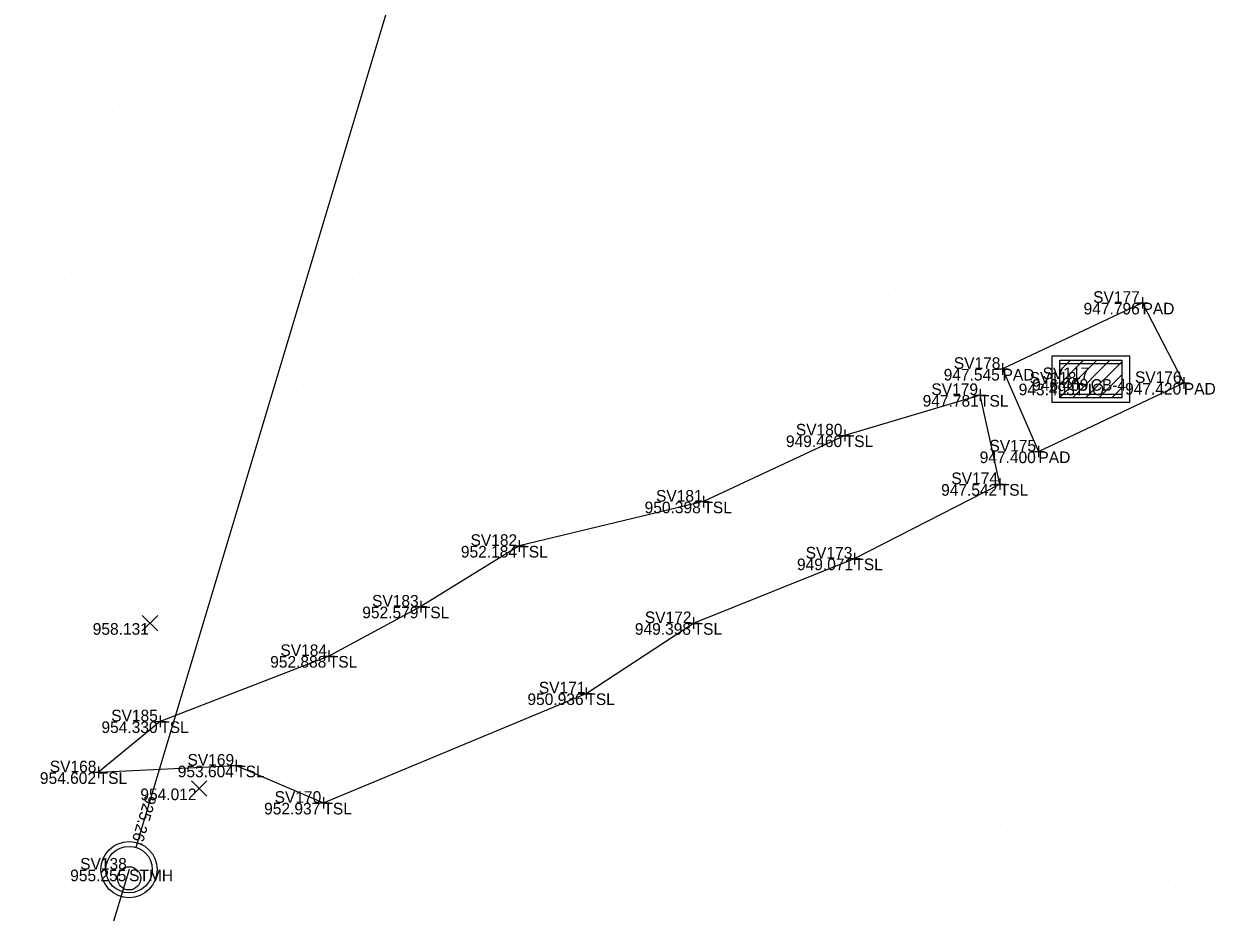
# Model space of a CAD drawing. Extents: x 2262025 to 2264532, y 740981 to 742724.
# Drawn here: x 2262974.6 to 2263077.7, y 741889.5 to 741965.9 of the extents above; entities that cross this region are included whole.
import ezdxf

# ---------------------------------------------------------------- set-up
doc = ezdxf.new("R2010")
doc.units = 0
for name, color, linetype in [('DR_X_Storm_Sewer', 7, 'Continuous'), ('GE_X_Alignment_1000_Bearings', 7, 'Continuous'), ('GE_X_Alignment_500_Cardinal_Points', 7, 'Continuous'), ('Ground Shots', 7, 'Continuous'), ('HY_X_Spring_Cells', 7, 'Continuous'), ('RS_Raster1', 7, 'Continuous'), ('RW_X_CL', 7, 'Continuous'), ('RW_X_CL_100_Cardinal_Points', 7, 'Continuous'), ('RW_X_CL_100_Curve_Data', 7, 'Continuous'), ('RW_X_CL_100_Stations', 7, 'Continuous'), ('RW_X_CL_500_Bearings', 7, 'Continuous'), ('RW_X_CL_500_Curve_Data', 7, 'Continuous'), ('RW_X_CL_500_Stations', 7, 'Continuous'), ('SV_X_Text_Comment', 7, 'Continuous')]:
    doc.layers.add(name, color=color, linetype=linetype)

msp = doc.modelspace()

# ---------------------------------------------------------------- linework, layer by layer
at = {"layer": 'DR_X_Storm_Sewer'}
msp.add_line((2263148.87, 742443.51), (2262984.25, 741895.04), dxfattribs=at)
msp.add_line((2263148.87, 742443.51), (2262984.25, 741895.04), dxfattribs=at)
at = {"layer": 'GE_X_Alignment_1000_Bearings'}
msp.add_line((2262986.36, 741905.89), (2262981.06, 741901.51), dxfattribs=at)
msp.add_lwpolyline([(2262981.06, 741901.51), (2262992.9, 741902.08), (2263000.41, 741898.88), (2263023.05, 741908.3), (2263032.29, 741914.35), (2263046.13, 741919.91), (2263058.65, 741926.32), (2263056.95, 741933.99), (2263045.3, 741930.51), (2263033.13, 741924.81), (2263017.28, 741921), (2263008.8, 741915.77), (2263000.88, 741911.52), (2262986.36, 741905.89)], dxfattribs=at)
at = {"layer": 'GE_X_Alignment_500_Cardinal_Points'}
for p, q in [((2262984.82, 741913.68), (2262986.16, 741915.02)), ((2262984.82, 741915.02), (2262986.16, 741913.68)), ((2262989.04, 741899.44), (2262990.37, 741900.77)), ((2262989.04, 741900.77), (2262990.37, 741899.44))]:
    msp.add_line(p, q, dxfattribs=at)
at = {"layer": 'Ground Shots'}
for p, q in [((2262977.78, 741964.05), (2262977.78, 741964.05)), ((2262987.89, 741964.11), (2262987.89, 741964.11)), ((2262997.78, 741964.05), (2262997.78, 741964.05)), ((2263002.86, 741964.01), (2263002.86, 741964.01)), ((2263007.85, 741964.01), (2263007.85, 741964.01)), ((2263013.06, 741964), (2263013.06, 741964)), ((2263017.95, 741964.01), (2263017.95, 741964.01)), ((2262992.72, 741963.93), (2262992.72, 741963.93)), ((2263023.1, 741963.95), (2263023.1, 741963.95)), ((2263027.97, 741963.9), (2263027.97, 741963.9)), ((2263039.17, 741962.7), (2263039.17, 741962.7)), ((2263044.03, 741962.73), (2263044.03, 741962.73)), ((2263049.08, 741962.59), (2263049.08, 741962.59)), ((2263054.04, 741962.61), (2263054.04, 741962.61)), ((2263074.22, 741962.68), (2263074.22, 741962.68)), ((2262977.87, 741959), (2262977.87, 741959)), ((2262982.88, 741959), (2262982.88, 741959)), ((2262987.81, 741959.1), (2262987.81, 741959.1)), ((2262993.22, 741958.93), (2262993.22, 741958.93)), ((2262997.81, 741959), (2262997.81, 741959)), ((2263002.53, 741958.99), (2263002.53, 741958.99)), ((2263012.72, 741959.33), (2263012.72, 741959.33)), ((2263027.82, 741958.8), (2263027.82, 741958.8)), ((2263063.8, 741958.18), (2263063.8, 741958.18)), ((2263073.89, 741957.83), (2263073.89, 741957.83)), ((2263034.06, 741957.47), (2263034.06, 741957.47)), ((2263039.02, 741957.76), (2263039.02, 741957.76)), ((2263044.2, 741957.53), (2263044.2, 741957.53)), ((2263048.71, 741957.73), (2263048.71, 741957.73)), ((2262977.9, 741954.03), (2262977.9, 741954.03)), ((2262982.64, 741953.86), (2262982.64, 741953.86)), ((2262987.68, 741953.97), (2262987.68, 741953.97)), ((2262992.99, 741953.89), (2262992.99, 741953.89)), ((2262997.81, 741954.05), (2262997.81, 741954.05)), ((2263003.2, 741953.68), (2263003.2, 741953.68)), ((2263007.91, 741953.88), (2263007.91, 741953.88)), ((2263012.97, 741953.9), (2263012.97, 741953.9)), ((2263022.62, 741953.86), (2263022.62, 741953.86)), ((2263027.93, 741954.09), (2263027.93, 741954.09)), ((2263074.31, 741953.11), (2263074.31, 741953.11)), ((2263044.21, 741952.42), (2263044.21, 741952.42)), ((2262977.96, 741948.8), (2262977.96, 741948.8)), ((2262982.92, 741948.92), (2262982.92, 741948.92)), ((2262987.8, 741949.09), (2262987.8, 741949.09)), ((2262992.95, 741948.94), (2262992.95, 741948.94)), ((2262997.96, 741948.85), (2262997.96, 741948.85)), ((2263002.58, 741948.79), (2263002.58, 741948.79)), ((2263007.83, 741948.92), (2263007.83, 741948.92)), ((2263017.86, 741948.95), (2263017.86, 741948.95)), ((2263027.83, 741948.74), (2263027.83, 741948.74)), ((2263039.03, 741947.72), (2263039.03, 741947.72)), ((2263044.31, 741947.68), (2263044.31, 741947.68)), ((2263049, 741947.6), (2263049, 741947.6)), ((2262978.08, 741943.92), (2262978.08, 741943.92)), ((2262982.84, 741944.05), (2262982.84, 741944.05)), ((2262987.8, 741944.07), (2262987.8, 741944.07)), ((2262992.77, 741944.11), (2262992.77, 741944.11)), ((2262997.83, 741943.88), (2262997.83, 741943.88)), ((2263002.9, 741943.97), (2263002.9, 741943.97)), ((2263008.06, 741943.97), (2263008.06, 741943.97)), ((2263012.8, 741944.32), (2263012.8, 741944.32)), ((2263018.17, 741944.32), (2263018.17, 741944.32)), ((2263022.52, 741944.1), (2263022.52, 741944.1)), ((2263028.09, 741943.85), (2263028.09, 741943.85)), ((2263049.04, 741942.58), (2263049.04, 741942.58)), ((2263054.22, 741943), (2263054.22, 741943)), ((2262977.59, 741939.17), (2262977.59, 741939.17)), ((2262982.88, 741938.94), (2262982.88, 741938.94)), ((2262992.98, 741938.86), (2262992.98, 741938.86)), ((2263003.1, 741938.87), (2263003.1, 741938.87)), ((2263039.17, 741937.71), (2263039.17, 741937.71)), ((2263043.96, 741937.7), (2263043.96, 741937.7)), ((2262998.13, 741934.31), (2262998.13, 741934.31)), ((2262978.02, 741933.85), (2262978.02, 741933.85)), ((2262982.77, 741933.92), (2262982.77, 741933.92)), ((2262987.92, 741934.02), (2262987.92, 741934.02)), ((2262992.93, 741933.85), (2262992.93, 741933.85)), ((2263002.69, 741934.03), (2263002.69, 741934.03)), ((2263038.95, 741933.19), (2263038.95, 741933.19)), ((2262977.8, 741929.1), (2262977.8, 741929.1)), ((2262982.98, 741929.1), (2262982.98, 741929.1)), ((2262987.91, 741929.08), (2262987.91, 741929.08)), ((2262977.78, 741924.52), (2262977.78, 741924.52)), ((2263073.57, 741906.83), (2263073.57, 741906.83)), ((2263058.66, 741901.69), (2263058.66, 741901.69)), ((2263063.77, 741901.96), (2263063.77, 741901.96)), ((2263068.59, 741901.85), (2263068.59, 741901.85)), ((2263073.62, 741901.52), (2263073.62, 741901.52)), ((2263058.68, 741897.03), (2263058.68, 741897.03)), ((2263063.6, 741897.11), (2263063.6, 741897.11)), ((2263068.56, 741897.06), (2263068.56, 741897.06)), ((2263043.46, 741896.56), (2263043.46, 741896.56)), ((2263048.46, 741896.88), (2263048.46, 741896.88)), ((2263053.56, 741896.87), (2263053.56, 741896.87)), ((2263073.57, 741896.78), (2263073.57, 741896.78)), ((2263033.48, 741892.09), (2263033.48, 741892.09)), ((2263038.64, 741891.93), (2263038.64, 741891.93)), ((2263043.54, 741891.89), (2263043.54, 741891.89)), ((2263048.75, 741891.89), (2263048.75, 741891.89)), ((2263058.49, 741891.93), (2263058.49, 741891.93)), ((2263063.73, 741892.08), (2263063.73, 741892.08)), ((2263068.55, 741891.88), (2263068.55, 741891.88)), ((2263073.15, 741892.2), (2263073.15, 741892.2)), ((2263028.77, 741891.51), (2263028.77, 741891.51)), ((2263053.54, 741891.7), (2263053.54, 741891.7))]:
    msp.add_line(p, q, dxfattribs=at)
at = {"layer": 'RW_X_CL_100_Cardinal_Points'}
for p, q in [((2263070.94, 741942.43), (2263070.94, 741941.43)), ((2263070.44, 741941.93), (2263071.44, 741941.93)), ((2263070.94, 741941.93), (2263070.94, 741941.93)), ((2263058.39, 741936.24), (2263059.39, 741936.24)), ((2263058.89, 741936.74), (2263058.89, 741935.74)), ((2263058.89, 741936.24), (2263058.89, 741936.24)), ((2263074.5, 741935.53), (2263074.5, 741934.53)), ((2263056.95, 741934.49), (2263056.95, 741933.49)), ((2263074, 741935.03), (2263075, 741935.03)), ((2263074.5, 741935.03), (2263074.5, 741935.03)), ((2263056.45, 741933.99), (2263057.45, 741933.99)), ((2263056.95, 741933.99), (2263056.95, 741933.99)), ((2263045.3, 741931.01), (2263045.3, 741930.01)), ((2263044.8, 741930.51), (2263045.8, 741930.51)), ((2263045.3, 741930.51), (2263045.3, 741930.51)), ((2263061.48, 741929.13), (2263062.48, 741929.13)), ((2263061.98, 741929.63), (2263061.98, 741928.63)), ((2263061.98, 741929.13), (2263061.98, 741929.13)), ((2263058.15, 741926.32), (2263059.15, 741926.32)), ((2263058.65, 741926.82), (2263058.65, 741925.82)), ((2263058.65, 741926.32), (2263058.65, 741926.32)), ((2263032.63, 741924.81), (2263033.63, 741924.81)), ((2263033.13, 741925.31), (2263033.13, 741924.31)), ((2263033.13, 741924.81), (2263033.13, 741924.81)), ((2263016.78, 741921), (2263017.78, 741921)), ((2263017.28, 741921.5), (2263017.28, 741920.5)), ((2263017.28, 741921), (2263017.28, 741921)), ((2263045.63, 741919.91), (2263046.63, 741919.91)), ((2263046.13, 741920.41), (2263046.13, 741919.41)), ((2263046.13, 741919.91), (2263046.13, 741919.91)), ((2263008.3, 741915.77), (2263009.3, 741915.77)), ((2263008.8, 741916.27), (2263008.8, 741915.27)), ((2263008.8, 741915.77), (2263008.8, 741915.77)), ((2263032.29, 741914.85), (2263032.29, 741913.85)), ((2263031.79, 741914.35), (2263032.79, 741914.35)), ((2263032.29, 741914.35), (2263032.29, 741914.35)), ((2263000.38, 741911.52), (2263001.38, 741911.52)), ((2263000.88, 741912.02), (2263000.88, 741911.02)), ((2263000.88, 741911.52), (2263000.88, 741911.52)), ((2263023.05, 741908.8), (2263023.05, 741907.8)), ((2263022.55, 741908.3), (2263023.55, 741908.3)), ((2263023.05, 741908.3), (2263023.05, 741908.3)), ((2262986.36, 741906.39), (2262986.36, 741905.39)), ((2262985.86, 741905.89), (2262986.86, 741905.89)), ((2262986.36, 741905.89), (2262986.36, 741905.89)), ((2262992.9, 741902.58), (2262992.9, 741901.58)), ((2262980.56, 741901.51), (2262981.56, 741901.51)), ((2262981.06, 741902.01), (2262981.06, 741901.01)), ((2262981.06, 741901.51), (2262981.06, 741901.51)), ((2262992.4, 741902.08), (2262993.4, 741902.08)), ((2262992.9, 741902.08), (2262992.9, 741902.08)), ((2263000.41, 741899.38), (2263000.41, 741898.38)), ((2262999.91, 741898.88), (2263000.91, 741898.88)), ((2263000.41, 741898.88), (2263000.41, 741898.88))]:
    msp.add_line(p, q, dxfattribs=at)
at = {"layer": 'RW_X_CL_100_Curve_Data'}
for p, q in [((2263063.82, 741933.79), (2263067, 741936.98)), ((2263063.82, 741934.93), (2263065.87, 741936.98)), ((2263063.82, 741936.06), (2263064.74, 741936.98)), ((2263063.82, 741933.79), (2263067, 741936.98)), ((2263063.82, 741934.93), (2263065.87, 741936.98)), ((2263063.82, 741936.06), (2263064.74, 741936.98)), ((2263064.9, 741933.75), (2263068.13, 741936.98)), ((2263064.9, 741933.75), (2263068.13, 741936.98)), ((2263066.03, 741933.75), (2263069.15, 741936.86)), ((2263066.03, 741933.75), (2263069.15, 741936.86)), ((2263067.17, 741933.75), (2263069.15, 741935.73)), ((2263067.17, 741933.75), (2263069.15, 741935.73)), ((2263068.3, 741933.75), (2263069.15, 741934.6)), ((2263068.3, 741933.75), (2263069.15, 741934.6))]:
    msp.add_line(p, q, dxfattribs=at)
for points in [[(2263063.15, 741937.36), (2263069.82, 741937.36), (2263069.82, 741933.36), (2263063.15, 741933.36)], [(2263063.15, 741937.36), (2263069.82, 741937.36), (2263069.82, 741933.36), (2263063.15, 741933.36)], [(2263063.82, 741936.98), (2263069.15, 741936.98), (2263069.15, 741933.75), (2263063.82, 741933.75)], [(2263063.82, 741936.98), (2263069.15, 741936.98), (2263069.15, 741933.75), (2263063.82, 741933.75)], [(2263063.82, 741936.7), (2263069.15, 741936.7), (2263069.15, 741934.03), (2263063.82, 741934.03)], [(2263063.82, 741936.7), (2263069.15, 741936.7), (2263069.15, 741934.03), (2263063.82, 741934.03)]]:
    msp.add_lwpolyline(points, close=True, dxfattribs=at)
for centre, radius in [((2262983.68, 741893.13), 2.42), ((2262983.68, 741893.13), 2.42), ((2262983.68, 741893.13), 2), ((2262983.68, 741893.13), 2), ((2262983.68, 741892.38), 1), ((2262983.68, 741892.38), 1)]:
    msp.add_circle(centre, radius, dxfattribs=at)
at = {"layer": 'RW_X_CL_100_Stations'}
for p, q in [((2263066.48, 741937.36), (2263066.48, 741937.36)), ((2263066.48, 741937.36), (2263066.48, 741937.36)), ((2263066.48, 741936.7), (2263066.48, 741936.7)), ((2263066.48, 741936.7), (2263066.48, 741936.7)), ((2263063.82, 741935.36), (2263063.82, 741935.36)), ((2263063.82, 741935.36), (2263063.82, 741935.36)), ((2263066.48, 741935.36), (2263066.48, 741935.36)), ((2263066.48, 741935.36), (2263066.48, 741935.36)), ((2263066.48, 741935.36), (2263066.48, 741935.36)), ((2263066.48, 741935.36), (2263066.48, 741935.36)), ((2263069.15, 741935.36), (2263069.15, 741935.36)), ((2263069.15, 741935.36), (2263069.15, 741935.36)), ((2263066.48, 741934.03), (2263066.48, 741934.03)), ((2263066.48, 741934.03), (2263066.48, 741934.03)), ((2263066.48, 741933.75), (2263066.48, 741933.75)), ((2263066.48, 741933.75), (2263066.48, 741933.75)), ((2263066.48, 741933.36), (2263066.48, 741933.36)), ((2263066.48, 741933.36), (2263066.48, 741933.36)), ((2262983.68, 741895.13), (2262983.68, 741895.13)), ((2262983.68, 741895.13), (2262983.68, 741895.13)), ((2262983.68, 741893.13), (2262983.68, 741893.13)), ((2262983.68, 741893.13), (2262983.68, 741893.13)), ((2262983.68, 741893.13), (2262983.68, 741893.13)), ((2262983.68, 741893.13), (2262983.68, 741893.13)), ((2262983.68, 741892.38), (2262983.68, 741892.38)), ((2262983.68, 741892.38), (2262983.68, 741892.38)), ((2262983.68, 741891.13), (2262983.68, 741891.13)), ((2262983.68, 741891.13), (2262983.68, 741891.13))]:
    msp.add_line(p, q, dxfattribs=at)
msp.add_circle((2262983.68, 741893.13), 2, dxfattribs=at)
msp.add_circle((2262983.68, 741893.13), 2, dxfattribs=at)
at = {"layer": 'RW_X_CL_500_Bearings'}
for p, q in [((2263065.33, 741935.47), (2263065.33, 741934.47)), ((2263064.83, 741934.97), (2263065.83, 741934.97)), ((2263065.33, 741934.97), (2263065.33, 741934.97))]:
    msp.add_line(p, q, dxfattribs=at)
at = {"layer": 'RW_X_CL_500_Curve_Data'}
msp.add_line((2263058.89, 741936.24), (2263061.98, 741929.13), dxfattribs=at)
msp.add_lwpolyline([(2263061.98, 741929.13), (2263074.5, 741935.03), (2263070.94, 741941.93), (2263058.89, 741936.24)], dxfattribs=at)
msp.add_lwpolyline([(2263061.98, 741929.13), (2263074.5, 741935.03), (2263070.94, 741941.93), (2263058.89, 741936.24)], dxfattribs=at)
at = {"layer": 'RW_X_CL_500_Stations'}
msp.add_line((2262983.68, 741893.13), (2262943.22, 741759.19), dxfattribs=at)

# ---------------------------------------------------------------- texts
at = {"layer": 'HY_X_Spring_Cells'}
for s, p in [('947.796', (2263065.87, 741940.93)), ('947.545', (2263053.82, 741935.24)), ('946.409', (2263061.44, 741934.36)), ('946.409', (2263061.44, 741934.36)), ('943.493', (2263060.28, 741933.97)), ('947.420', (2263069.44, 741934.03)), ('947.781', (2263052.01, 741932.99)), ('949.460', (2263040.24, 741929.51)), ('947.400', (2263056.92, 741928.13)), ('947.542', (2263053.6, 741925.32)), ('950.398', (2263028.07, 741923.81)), ('952.184', (2263012.25, 741920)), ('949.071', (2263041.19, 741918.91)), ('952.579', (2263003.76, 741914.77)), ('958.131', (2262980.55, 741913.35)), ('949.398', (2263027.23, 741913.35)), ('952.888', (2262995.83, 741910.52)), ('950.936', (2263017.98, 741907.3)), ('954.330', (2262981.3, 741904.89)), ('954.602', (2262976, 741900.51)), ('953.604', (2262987.87, 741901.08)), ('954.012', (2262984.65, 741899.11)), ('952.937', (2262995.31, 741897.88)), ('955.255', (2262978.61, 741892.13)), ('955.255', (2262978.61, 741892.13))]:
    msp.add_text(s, height=1, dxfattribs=at).set_placement(p)
at = {"layer": 'RS_Raster1'}
msp.add_text("925.26'", height=1, rotation=253.2931, dxfattribs=at).set_placement((2262985.1, 741899.62))
msp.add_text("925.26'", height=1, rotation=253.2931, dxfattribs=at).set_placement((2262985.1, 741899.62))
at = {"layer": 'RW_X_CL'}
for s, p in [('PAD', (2263070.94, 741940.93)), ('PAD', (2263058.89, 741935.24)), ('CB-4', (2263066.48, 741934.36)), ('CB-4', (2263066.48, 741934.36)), ('PIO', (2263065.33, 741933.97)), ('PAD', (2263074.5, 741934.03)), ('TSL', (2263056.95, 741932.99)), ('TSL', (2263045.3, 741929.51)), ('PAD', (2263061.98, 741928.13)), ('TSL', (2263058.65, 741925.32)), ('TSL', (2263033.13, 741923.81)), ('TSL', (2263017.28, 741920)), ('TSL', (2263046.13, 741918.91)), ('TSL', (2263008.8, 741914.77)), ('TSL', (2263032.29, 741913.35)), ('TSL', (2263000.88, 741910.52)), ('TSL', (2263023.05, 741907.3)), ('TSL', (2262986.36, 741904.89)), ('TSL', (2262981.06, 741900.51)), ('TSL', (2262992.9, 741901.08)), ('TSL', (2263000.41, 741897.88)), ('STMH', (2262983.68, 741892.13)), ('STMH', (2262983.68, 741892.13))]:
    msp.add_text(s, height=1, dxfattribs=at).set_placement(p)
at = {"layer": 'SV_X_Text_Comment'}
for s, p in [('SV177', (2263066.69, 741941.93)), ('SV178', (2263054.69, 741936.24)), ('SV117', (2263062.34, 741935.36)), ('SV117', (2263062.34, 741935.36)), ('SV118', (2263061.23, 741934.97)), ('SV176', (2263070.29, 741935.03)), ('SV179', (2263052.76, 741933.99)), ('SV180', (2263041.09, 741930.51)), ('SV175', (2263057.76, 741929.13)), ('SV174', (2263054.48, 741926.32)), ('SV181', (2263029.05, 741924.81)), ('SV182', (2263013.08, 741921)), ('SV173', (2263041.94, 741919.91)), ('SV183', (2263004.6, 741915.77)), ('SV172', (2263028.09, 741914.35)), ('SV184', (2262996.71, 741911.52)), ('SV171', (2263018.96, 741908.3)), ('SV185', (2262982.14, 741905.89)), ('SV168', (2262976.85, 741901.51)), ('SV169', (2262988.71, 741902.08)), ('SV170', (2262996.21, 741898.88)), ('SV138', (2262979.47, 741893.13)), ('SV138', (2262979.47, 741893.13))]:
    msp.add_text(s, height=1, dxfattribs=at).set_placement(p)

doc.saveas('drawing.dxf')
